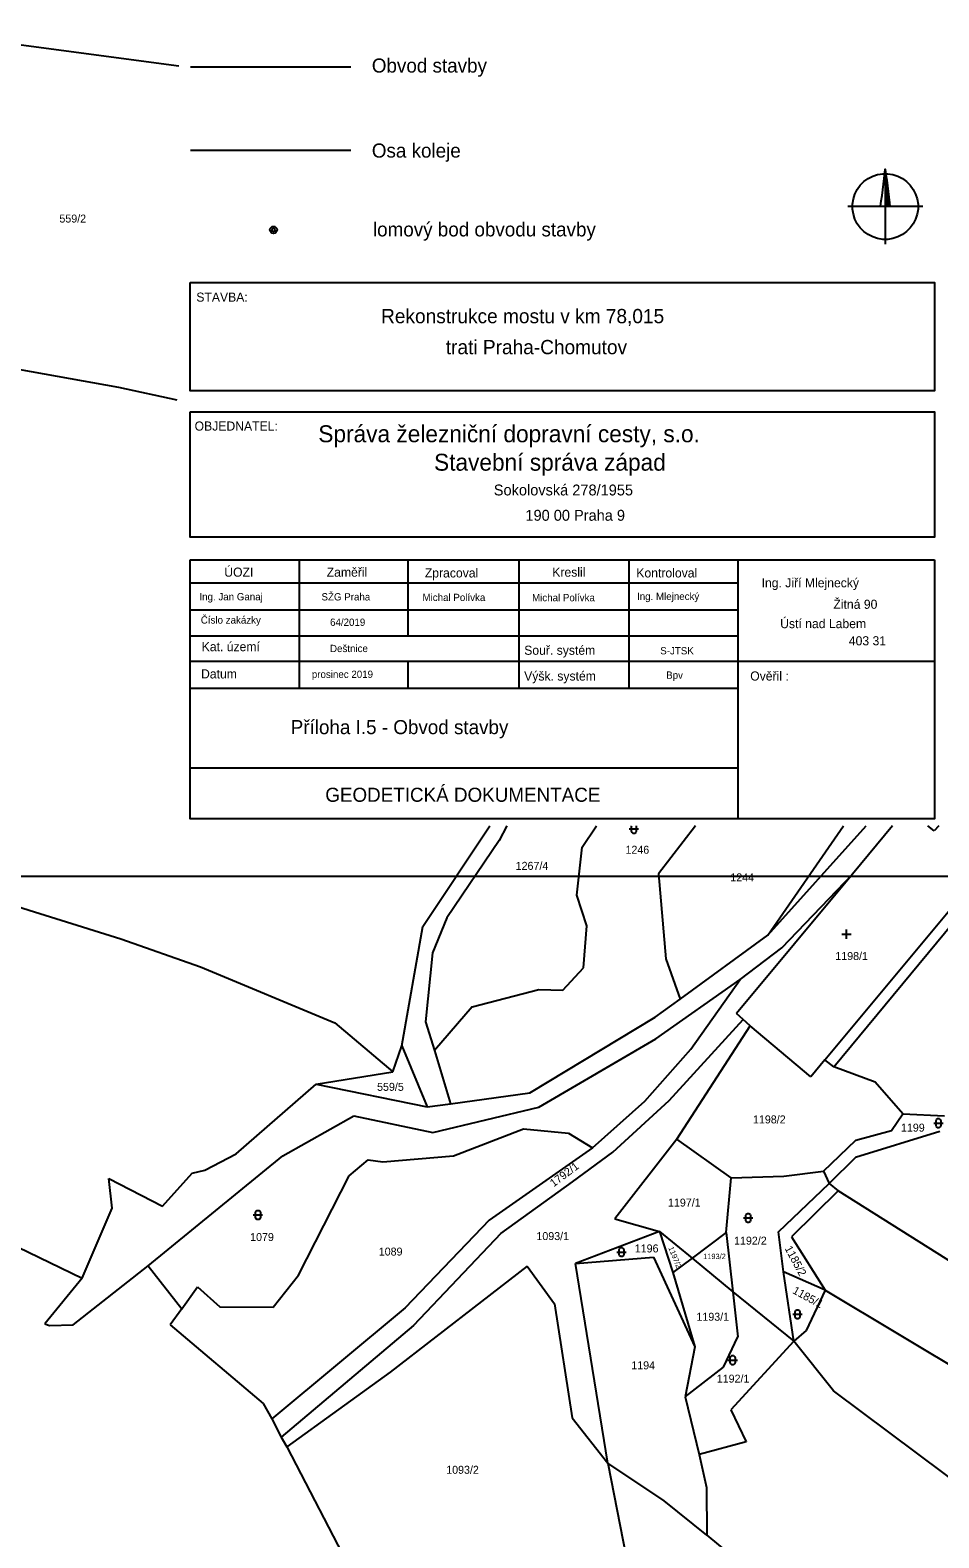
# Model space of a CAD drawing. Extents: x -799786 to -795190, y -1021716 to -1017834.
# Drawn here: x -798627.9 to -798434.2, y -1019350.1 to -1019029 of the extents above; entities that cross this region are included whole.
import ezdxf

# ---------------------------------------------------------------- set-up
doc = ezdxf.new("R2010")
doc.units = 0
for name, color, linetype in [('body', 7, 'Continuous'), ('Default', 7, 'Continuous'), ('KN_HRANICE', 7, 'Continuous'), ('KN_KULTURY', 7, 'Continuous'), ('KN_PARCELY', 7, 'Continuous'), ('LEGENDA', 7, 'Continuous'), ('tabulka', 7, 'Continuous')]:
    doc.layers.add(name, color=color, linetype=linetype)

# ---------------------------------------------------------------- blocks, each defined once
blk = doc.blocks.new('315')
at = {"layer": 'Default'}
for p, q in [((-1, 1), (1, 1)), ((0, 0), (0, 2))]:
    blk.add_line(p, q, dxfattribs=at)
blk = doc.blocks.new('316')
at = {"layer": 'Default'}
for points in [[(-1, 1), (0.27, 1), (1, 1)], [(-0.5, 1.5), (-0.4, 1.79), (-0.15, 1.97), (0.16, 1.97), (0.41, 1.79), (0.51, 1.5), (0.51, 0.5), (0.41, 0.21), (0.16, 0.03), (-0.15, 0.03), (-0.4, 0.21), (-0.5, 0.5), (-0.5, 1.5)]]:
    blk.add_lwpolyline(points, dxfattribs=at)
blk = doc.blocks.new('SEVER')
at = {"layer": 'Default'}
for points in [[(5.5, 69.8), (16.3, 68.1), (26.7, 64.7), (36.5, 59.7), (45.4, 53.2), (53.2, 45.4), (59.7, 36.5), (64.7, 26.7), (68.1, 16.3), (69.8, 5.5), (69.8, -5.5), (68.1, -16.3), (64.7, -26.7), (59.7, -36.5), (53.2, -45.4), (45.4, -53.2), (36.5, -59.7), (26.7, -64.7), (16.3, -68.1), (5.5, -69.8), (-5.5, -69.8), (-16.3, -68.1), (-26.7, -64.7), (-36.5, -59.7), (-45.4, -53.2), (-53.2, -45.4), (-59.7, -36.5), (-64.7, -26.7), (-68.1, -16.3), (-69.8, -5.5), (-69.8, 5.5), (-68.1, 16.3), (-64.7, 26.7), (-59.7, 36.5), (-53.2, 45.4), (-45.4, 53.2), (-36.5, 59.7), (-26.7, 64.7), (-16.3, 68.1), (-5.5, 69.8), (5.5, 69.8)], [(-10, 0), (-8.5, 12), (-7, 24), (-5.5, 36), (-4, 48), (-2.5, 60), (-1, 72), (0, 80), (1.5, 68), (3, 56), (4.5, 44), (6, 32), (7.5, 20), (9, 8), (10, 0), (9.2, 0.8), (9.2, 5.6), (8.4, 12), (8.4, 0.8), (7.6, 0.8), (7.6, 13.5), (7.6, 18.4), (6.8, 24.8), (6.8, 12.1), (6.8, 0.8), (6, 0.8), (6, 13.5), (6, 26.2), (6, 31.2), (5.2, 36.8), (5.2, 24.1), (5.2, 11.4), (5.2, 0.8), (4.4, 0.8), (4.4, 13.5), (4.4, 26.2), (4.4, 38.9), (4.4, 43.2), (3.6, 50.4), (3.6, 37.7), (3.6, 25), (3.6, 12.3), (3.6, 0.8), (2.8, 0.8), (2.8, 13.5), (2.8, 26.2), (2.8, 38.9), (2.8, 51.6), (2.8, 56), (2, 63.2), (2, 50.5), (2, 37.8), (2, 25.1), (2, 12.4), (2, 0.8), (1.2, 0.8), (1.2, 13.5), (1.2, 26.2), (1.2, 38.9), (1.2, 51.6), (1.2, 64.3), (1.2, 69.6), (0.4, 76), (0.4, 63.3), (0.4, 50.6), (0.4, 37.9), (0.4, 25.2), (0.4, 12.5), (0.4, 0.8)], [(0, 80), (0, 67.3), (0, 54.6), (0, 41.9), (0, 29.2), (0, 16.5), (0, 3.8), (0, -8.9), (0, -21.6), (0, -34.3), (0, -47), (0, -59.7), (0, -72.4), (0, -80)], [(80, 0), (67.3, 0), (54.6, 0), (41.9, 0), (29.2, 0), (16.5, 0), (3.8, 0), (-8.9, 0), (-21.6, 0), (-34.3, 0), (-47, 0), (-59.7, 0), (-72.4, 0), (-80, 0)]]:
    blk.add_lwpolyline(points, dxfattribs=at)

msp = doc.modelspace()

# ---------------------------------------------------------------- linework, layer by layer
at = {"layer": 'body'}
for radius in [0.75, 0.35]:
    msp.add_circle((-798576, -1019071.53), radius, dxfattribs=at)
at = {"layer": 'KN_HRANICE'}
for p, q in [((-798650, -1019029.38), (-798596.15, -1019036.62)), ((-798608.96, -1019105.11), (-798639.62, -1019099.64)), ((-798596.52, -1019107.77), (-798608.96, -1019105.11)), ((-798544.17, -1019219.92), (-798529.93, -1019198.47)), ((-798526.27, -1019198.47), (-798527.91, -1019201.56)), ((-798510.21, -1019203), (-798507.21, -1019198.47)), ((-798486.07, -1019198.47), (-798493.93, -1019208.72)), ((-798470.68, -1019221.78), (-798449.69, -1019198.47)), ((-798470.68, -1019221.78), (-798454.57, -1019198.47)), ((-798444.09, -1019198.47), (-798452.63, -1019208.73)), ((-798435.21, -1019199.56), (-798436.61, -1019198.47)), ((-798434.24, -1019198.47), (-798435.21, -1019199.56)), ((-798527.91, -1019201.56), (-798539.04, -1019218.08)), ((-798511.35, -1019213.22), (-798510.21, -1019203)), ((-798458.53, -1019248.28), (-798425.19, -1019208.25)), ((-798493.93, -1019208.72), (-798492.37, -1019226.82)), ((-798452.63, -1019208.73), (-798477.35, -1019238.45)), ((-798467.68, -1019224.43), (-798452.63, -1019208.73)), ((-798641.03, -1019212.36), (-798608.55, -1019222.56)), ((-798509.26, -1019219.75), (-798511.35, -1019213.22)), ((-798456.62, -1019249.78), (-798429.28, -1019216.81)), ((-798548.65, -1019245.36), (-798544.17, -1019219.92)), ((-798539.04, -1019218.08), (-798542.11, -1019225.49)), ((-798509.93, -1019228.7), (-798509.26, -1019219.75)), ((-798608.55, -1019222.56), (-798591.52, -1019228.5)), ((-798489.36, -1019235.41), (-798470.68, -1019221.78)), ((-798476.58, -1019231.21), (-798467.68, -1019224.43)), ((-798542.11, -1019225.49), (-798543.64, -1019240.18)), ((-798492.37, -1019226.82), (-798489.36, -1019235.41)), ((-798591.52, -1019228.5), (-798562.92, -1019240.42)), ((-798514.33, -1019233.5), (-798509.93, -1019228.7)), ((-798533.7, -1019237.04), (-798519.48, -1019233.3)), ((-798519.48, -1019233.3), (-798514.33, -1019233.5)), ((-798494.5, -1019243.85), (-798476.58, -1019231.21)), ((-798487.05, -1019246.02), (-798476.58, -1019231.21)), ((-798533.7, -1019237.04), (-798541.71, -1019246.33)), ((-798494.71, -1019239.22), (-798489.36, -1019235.41)), ((-798562.92, -1019240.42), (-798550.57, -1019250.84)), ((-798543.64, -1019240.18), (-798541.71, -1019246.33)), ((-798521.41, -1019255.32), (-798494.71, -1019239.22)), ((-798491.71, -1019256.99), (-798475.96, -1019239.74)), ((-798475.96, -1019239.74), (-798477.35, -1019238.45)), ((-798474.46, -1019241.09), (-798475.96, -1019239.74)), ((-798490.05, -1019265.19), (-798474.46, -1019241.09)), ((-798461.53, -1019251.9), (-798474.46, -1019241.09)), ((-798550.57, -1019250.84), (-798548.65, -1019245.36)), ((-798548.65, -1019245.36), (-798543.24, -1019258.32)), ((-798541.71, -1019246.33), (-798538.3, -1019257.65)), ((-798519.48, -1019258.39), (-798494.5, -1019243.85)), ((-798496.88, -1019257.09), (-798487.05, -1019246.02)), ((-798458.53, -1019248.28), (-798461.53, -1019251.9)), ((-798456.62, -1019249.78), (-798458.53, -1019248.28)), ((-798447.78, -1019253.09), (-798456.62, -1019249.78)), ((-798566.93, -1019253.51), (-798550.57, -1019250.84)), ((-798441.91, -1019259.81), (-798447.78, -1019253.09)), ((-798583.99, -1019268.34), (-798566.93, -1019253.51)), ((-798566.93, -1019253.51), (-798543.24, -1019258.32)), ((-798538.3, -1019257.65), (-798521.41, -1019255.32)), ((-798543.24, -1019258.32), (-798538.3, -1019257.65)), ((-798542.02, -1019263.8), (-798519.48, -1019258.39)), ((-798508.04, -1019267.02), (-798496.88, -1019257.09)), ((-798503.7, -1019267.95), (-798491.71, -1019256.99)), ((-798444.34, -1019263.37), (-798441.91, -1019259.81)), ((-798441.91, -1019259.81), (-798433.02, -1019260.22)), ((-798574.04, -1019268.76), (-798558.85, -1019260.26)), ((-798558.85, -1019260.26), (-798542.02, -1019263.8)), ((-798537.62, -1019268.78), (-798522.73, -1019262.99)), ((-798522.73, -1019262.99), (-798513.11, -1019263.92)), ((-798513.11, -1019263.92), (-798508.04, -1019267.02)), ((-798490.05, -1019265.19), (-798503.28, -1019282.16)), ((-798478.47, -1019273.47), (-798490.05, -1019265.19)), ((-798458.82, -1019272.01), (-798451.89, -1019265.39)), ((-798434, -1019263.58), (-798451.99, -1019269.12)), ((-798451.89, -1019265.39), (-798444.34, -1019263.37)), ((-798602.68, -1019292.18), (-798574.04, -1019268.76)), ((-798590.6, -1019271.84), (-798583.99, -1019268.34)), ((-798552.72, -1019270.02), (-798537.62, -1019268.78)), ((-798508.04, -1019267.02), (-798530.05, -1019282.48)), ((-798512.26, -1019274.31), (-798503.7, -1019267.95)), ((-798451.99, -1019269.12), (-798457.57, -1019274.65)), ((-798599.68, -1019279.49), (-798593.31, -1019272.48)), ((-798593.31, -1019272.48), (-798590.6, -1019271.84)), ((-798559.85, -1019273.02), (-798555.82, -1019269.61)), ((-798555.82, -1019269.61), (-798552.72, -1019270.02)), ((-798467.29, -1019273.1), (-798458.82, -1019272.01)), ((-798458.82, -1019272.01), (-798457.57, -1019274.65)), ((-798610.36, -1019279.89), (-798611.08, -1019273.6)), ((-798611.08, -1019273.6), (-798599.68, -1019279.49)), ((-798570.69, -1019294.19), (-798559.85, -1019273.02)), ((-798527.56, -1019285.28), (-798512.26, -1019274.31)), ((-798479.53, -1019285.1), (-798478.47, -1019273.47)), ((-798478.47, -1019273.47), (-798467.29, -1019273.1)), ((-798468.41, -1019284.95), (-798457.57, -1019274.65)), ((-798457.57, -1019274.65), (-798455.66, -1019276.2)), ((-798653.35, -1019277.09), (-798616.8, -1019294.82)), ((-798455.66, -1019276.2), (-798465.62, -1019286.03)), ((-798413.87, -1019302.58), (-798455.66, -1019276.2)), ((-798616.8, -1019294.82), (-798610.36, -1019279.89)), ((-798503.28, -1019282.16), (-798493.77, -1019284.85)), ((-798530.05, -1019282.48), (-798547.93, -1019301.1)), ((-798527.56, -1019285.28), (-798546.18, -1019304.93)), ((-798493.77, -1019284.85), (-798511.66, -1019291.68)), ((-798493.77, -1019284.85), (-798490.9, -1019293.64)), ((-798493.77, -1019284.85), (-798486.8, -1019290.56)), ((-798479.53, -1019285.1), (-798486.8, -1019290.56)), ((-798479.53, -1019285.1), (-798478.12, -1019297.69)), ((-798467.32, -1019293.43), (-798468.41, -1019284.95)), ((-798465.62, -1019286.03), (-798458.48, -1019297.36)), ((-798511.66, -1019291.68), (-798495.01, -1019290.33)), ((-798504.73, -1019334.25), (-798511.66, -1019291.68)), ((-798495.01, -1019290.33), (-798486.25, -1019309.47)), ((-798486.8, -1019290.56), (-798490.9, -1019293.64)), ((-798486.8, -1019290.56), (-798478.12, -1019297.69)), ((-798616.8, -1019294.82), (-798624.76, -1019304.52)), ((-798618.7, -1019304.72), (-798602.68, -1019292.18)), ((-798602.68, -1019292.18), (-798595.52, -1019301.34)), ((-798576.06, -1019301.02), (-798570.69, -1019294.19)), ((-798521.98, -1019292.29), (-798551.14, -1019314.85)), ((-798521.98, -1019292.29), (-798516.09, -1019300.26)), ((-798490.9, -1019293.64), (-798486.25, -1019309.47)), ((-798458.48, -1019297.36), (-798467.32, -1019293.43)), ((-798465.13, -1019308.25), (-798467.32, -1019293.43)), ((-798595.52, -1019301.34), (-798592.23, -1019296.66)), ((-798592.23, -1019296.66), (-798587.44, -1019300.91)), ((-798478.12, -1019297.69), (-798477.04, -1019307.29)), ((-798478.12, -1019297.69), (-798465.13, -1019308.25)), ((-798458.48, -1019297.36), (-798462.51, -1019305.95)), ((-798458.48, -1019297.36), (-798422.2, -1019319.14)), ((-798595.52, -1019301.34), (-798598, -1019304.72)), ((-798587.44, -1019300.91), (-798576.06, -1019301.02)), ((-798547.93, -1019301.1), (-798576.33, -1019324.79)), ((-798516.09, -1019300.26), (-798512.36, -1019324.57)), ((-798624.76, -1019304.52), (-798623.72, -1019304.92)), ((-798623.72, -1019304.92), (-798618.7, -1019304.72)), ((-798598, -1019304.72), (-798578.22, -1019321.5)), ((-798546.18, -1019304.93), (-798574.35, -1019328.67)), ((-798480.09, -1019313.76), (-798477.04, -1019307.29)), ((-798462.51, -1019305.95), (-798465.13, -1019308.25)), ((-798486.25, -1019309.47), (-798488.31, -1019320.12)), ((-798465.13, -1019308.25), (-798478.57, -1019322.88)), ((-798456.65, -1019318.8), (-798465.13, -1019308.25)), ((-798488.31, -1019320.12), (-798480.09, -1019313.76)), ((-798551.14, -1019314.85), (-798573.15, -1019330.76)), ((-798488.31, -1019320.12), (-798485.29, -1019332.39)), ((-798422.56, -1019344.32), (-798456.65, -1019318.8)), ((-798578.22, -1019321.5), (-798576.33, -1019324.79)), ((-798478.57, -1019322.88), (-798475.26, -1019329.7)), ((-798576.33, -1019324.79), (-798574.35, -1019328.67)), ((-798512.36, -1019324.57), (-798504.73, -1019334.25)), ((-798574.35, -1019328.67), (-798573.15, -1019330.76)), ((-798475.26, -1019329.7), (-798485.29, -1019332.39)), ((-798573.15, -1019330.76), (-798558.55, -1019358.8)), ((-798485.29, -1019332.39), (-798483.74, -1019339.43)), ((-798504.73, -1019334.25), (-798500.11, -1019358.06)), ((-798492.74, -1019342.22), (-798504.73, -1019334.25)), ((-798483.74, -1019339.43), (-798483.64, -1019349.57)), ((-798483.64, -1019349.57), (-798492.74, -1019342.22)), ((-798483.64, -1019349.57), (-798468.64, -1019361.98))]:
    msp.add_line(p, q, dxfattribs=at)
at = {"layer": 'KN_KULTURY'}
for points in [[(-798499.71, -1019198.61), (-798499.66, -1019198.47)], [(-798498.75, -1019198.47), (-798498.7, -1019198.61), (-798498.7, -1019199.61), (-798498.8, -1019199.9), (-798499.05, -1019200.08), (-798499.36, -1019200.08), (-798499.61, -1019199.9), (-798499.71, -1019199.61), (-798499.71, -1019198.61)], [(-798500.21, -1019199.11), (-798498.94, -1019199.11), (-798498.21, -1019199.11)]]:
    msp.add_lwpolyline(points, dxfattribs=at)
at = {"layer": 'LEGENDA'}
for p, q in [((-798593.7, -1019036.77), (-798559.51, -1019036.77)), ((-798593.7, -1019054.55), (-798559.51, -1019054.55))]:
    msp.add_line(p, q, dxfattribs=at)
msp.add_lwpolyline([(-799014.18, -1018789.26), (-798420.18, -1018789.26), (-798420.18, -1019209.26), (-799014.18, -1019209.26)], close=True, dxfattribs=at)
at = {"layer": 'tabulka'}
for p, q in [((-798593.79, -1019141.81), (-798435.14, -1019141.81)), ((-798570.51, -1019141.81), (-798570.51, -1019169.12)), ((-798547.36, -1019141.81), (-798547.36, -1019158.01)), ((-798523.76, -1019141.81), (-798523.76, -1019169.12)), ((-798500.31, -1019141.81), (-798500.31, -1019169.12)), ((-798477.01, -1019196.94), (-798477.01, -1019141.81)), ((-798593.79, -1019146.71), (-798477.01, -1019146.71)), ((-798593.79, -1019152.43), (-798477.01, -1019152.43)), ((-798593.79, -1019158.01), (-798477.01, -1019158.01)), ((-798593.79, -1019163.42), (-798435.14, -1019163.42)), ((-798547.36, -1019163.42), (-798547.36, -1019169.12)), ((-798593.79, -1019169.12), (-798477.01, -1019169.12)), ((-798593.79, -1019186.12), (-798477.01, -1019186.12))]:
    msp.add_line(p, q, dxfattribs=at)
for points in [[(-798593.79, -1019082.72), (-798435.14, -1019082.72), (-798435.14, -1019105.78), (-798593.79, -1019105.78)], [(-798593.79, -1019110.3), (-798435.14, -1019110.3), (-798435.14, -1019136.99), (-798593.79, -1019136.99)]]:
    msp.add_lwpolyline(points, close=True, dxfattribs=at)
msp.add_lwpolyline([(-798435.14, -1019141.81), (-798435.14, -1019196.94), (-798593.79, -1019196.94), (-798593.79, -1019141.81)], dxfattribs=at)

# ---------------------------------------------------------------- block references
at = {"layer": 'KN_KULTURY'}
for name, p in [('315', (-798453.92, -1019222.56)), ('316', (-798434.33, -1019262.8)), ('316', (-798579.31, -1019282.35)), ('316', (-798474.86, -1019282.99)), ('316', (-798501.87, -1019290.25)), ('316', (-798464.34, -1019303.51)), ('316', (-798478.16, -1019313.27))]:
    msp.add_blockref(name, p, dxfattribs=at)
at = {"layer": 'LEGENDA', "xscale": 0.1, "yscale": 0.10000000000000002}
msp.add_blockref('SEVER', (-798445.64, -1019066.57), dxfattribs=at)

# ---------------------------------------------------------------- texts
at = {"layer": 'KN_PARCELY'}
for s, height, p in [('559/2', 1.7, (-798621.62, -1019069.97)), ('1246', 1.7, (-798501, -1019204.41)), ('1267/4', 1.7, (-798524.4, -1019207.84)), ('1244', 1.7, (-798478.66, -1019210.29)), ('1198/1', 1.7, (-798456.29, -1019227.05)), ('559/5', 1.7, (-798553.93, -1019254.91)), ('1198/2', 1.7, (-798473.83, -1019261.85)), ('1199', 1.7, (-798442.3, -1019263.6)), ('1197/1', 1.7, (-798491.94, -1019279.56)), ('1079', 1.7, (-798580.98, -1019286.9)), ('1093/1', 1.7, (-798519.98, -1019286.7)), ('1089', 1.7, (-798553.57, -1019290)), ('1196', 1.7, (-798499.02, -1019289.33)), ('1192/2', 1.7, (-798477.86, -1019287.67)), ('1193/2', 1.14, (-798484.44, -1019290.75)), ('1193/1', 1.7, (-798485.88, -1019303.88)), ('1194', 1.7, (-798499.76, -1019314.23)), ('1192/1', 1.7, (-798481.55, -1019317.06)), ('1093/2', 1.7, (-798539.2, -1019336.48))]:
    msp.add_text(s, height=height, dxfattribs=at).set_placement(p)
for s, height, rotation, p in [('1792/1', 1.7, 36.956, (-798516.31, -1019275.48)), ('1197/2', 1.14, 292.037, (-798491.89, -1019288.34)), ('1185/2', 1.7, 298.282, (-798467.14, -1019288.46)), ('1185/1', 1.7, 331.399, (-798465.55, -1019297.94))]:
    msp.add_text(s, height=height, rotation=rotation, dxfattribs=at).set_placement(p)
at = {"layer": 'LEGENDA'}
for s, p in [('Obvod stavby', (-798555.05, -1019038.02)), ('Osa koleje', (-798555.05, -1019056.13)), ('lomový bod obvodu stavby', (-798554.81, -1019072.92))]:
    msp.add_text(s, height=3, dxfattribs=at).set_placement(p)
at = {"layer": 'tabulka'}
for s, height, p in [('STAVBA:', 1.94, (-798592.45, -1019086.82)), ('Rekonstrukce mostu v km 78,015', 3.04, (-798553.08, -1019091.41)), ('trati Praha-Chomutov', 3.04, (-798539.29, -1019098.01)), ('OBJEDNATEL:', 1.94, (-798592.81, -1019114.28)), ('Správa železniční dopravní cesty, s.o.', 3.61, (-798566.45, -1019116.76)), ('Stavební správa západ', 3.61, (-798541.79, -1019122.82)), ('Sokolovská 278/1955', 2.32, (-798529.06, -1019128.09)), ('190 00 Praha 9', 2.32, (-798522.32, -1019133.48)), ('ÚOZI', 1.94, (-798586.49, -1019145.4)), ('Zaměřil', 1.94, (-798564.66, -1019145.4)), ('Zpracoval', 1.94, (-798543.76, -1019145.56)), ('Kreslil', 1.94, (-798516.6, -1019145.4)), ('Kontroloval', 1.94, (-798498.69, -1019145.56)), ('Ing. Jiří Mlejnecký', 1.94, (-798472, -1019147.66)), ('Ing. Jan Ganaj', 1.552, (-798591.78, -1019150.44)), ('SŽG Praha', 1.552, (-798565.77, -1019150.46)), ('Michal Polívka', 1.552, (-798544.25, -1019150.59)), ('Michal Polívka', 1.552, (-798520.91, -1019150.63)), ('Ing. Mlejnecký', 1.552, (-798498.54, -1019150.36)), ('Žitná 90', 1.94, (-798456.7, -1019152.24)), ('Číslo zakázky', 1.552, (-798591.49, -1019155.39)), ('64/2019', 1.552, (-798563.95, -1019155.87)), ('Ústí nad Labem', 1.94, (-798468.04, -1019156.36)), ('Kat. území', 1.94, (-798591.3, -1019161.27)), ('Deštnice', 1.552, (-798563.96, -1019161.46)), ('Souř. systém', 1.94, (-798522.58, -1019162.03)), ('403 31', 1.94, (-798453.41, -1019160.02)), ('S-JTSK', 1.552, (-798493.59, -1019161.95)), ('Datum', 1.94, (-798591.44, -1019167.07)), ('prosinec 2019', 1.552, (-798567.83, -1019166.96)), ('Výšk. systém', 1.94, (-798522.59, -1019167.52)), ('Bpv', 1.552, (-798492.33, -1019167.14)), ('Ověřil :', 1.94, (-798474.42, -1019167.52)), ('Příloha I.5 - Obvod stavby', 3, (-798572.33, -1019178.94)), ('GEODETICKÁ DOKUMENTACE ', 3, (-798564.97, -1019193.35))]:
    msp.add_text(s, height=height, dxfattribs=at).set_placement(p)

doc.saveas('drawing.dxf')
